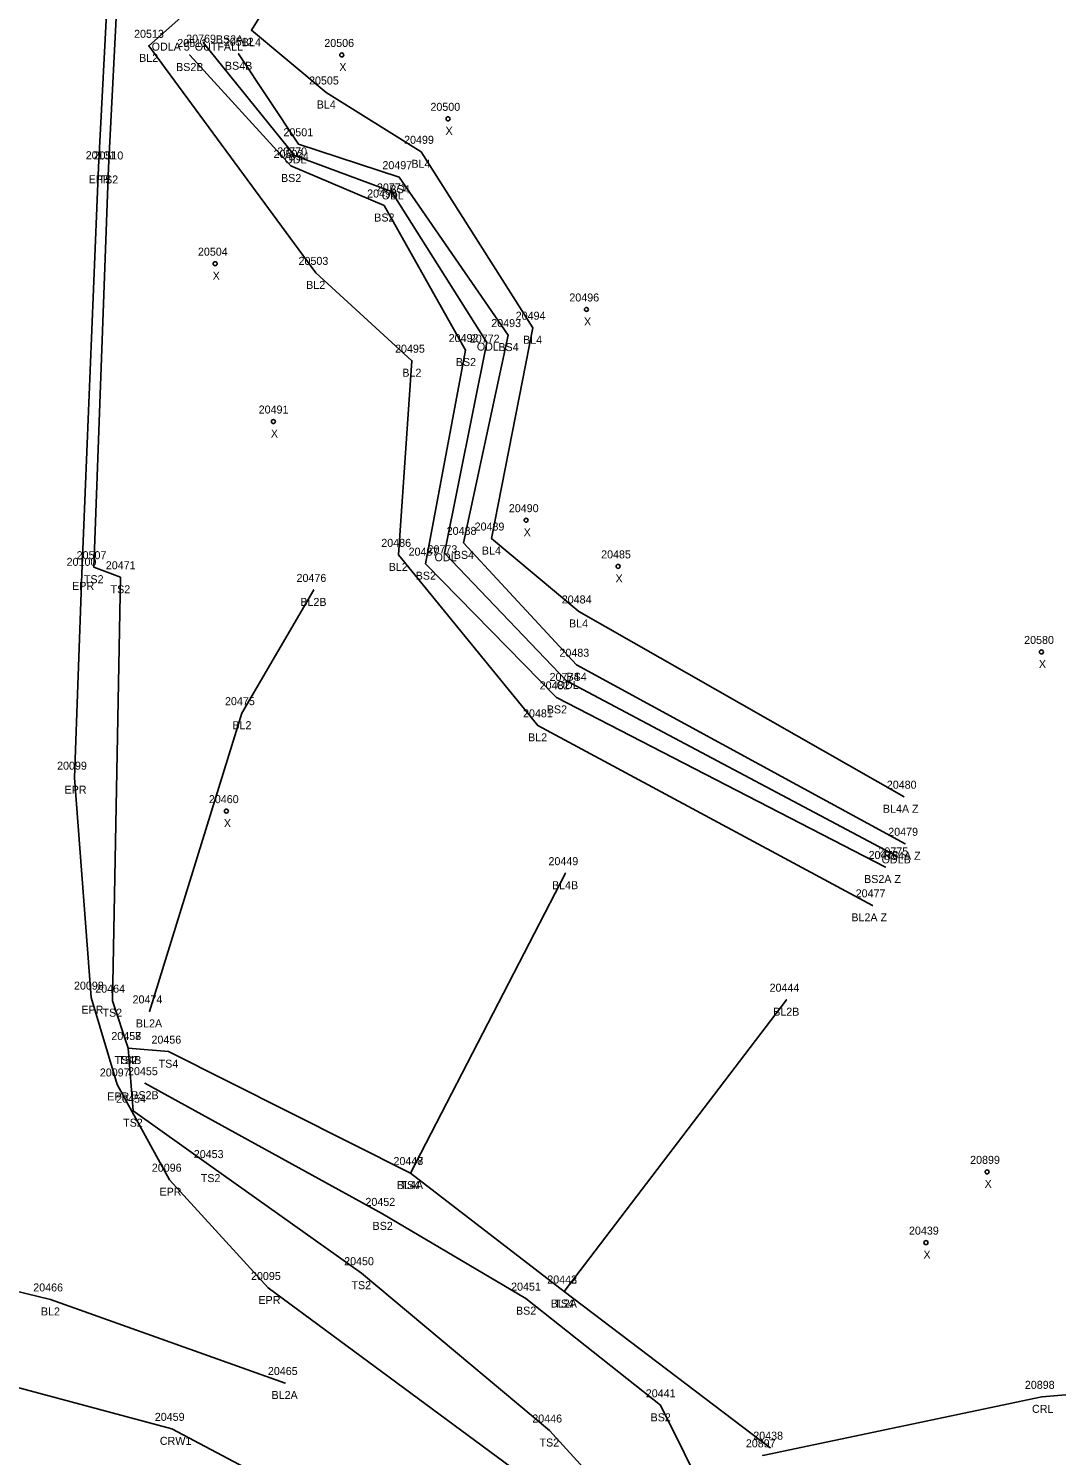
# Model space of a CAD drawing. Extents: x 1813127 to 1818290, y 1178171 to 1179900.
# Drawn here: x 1813676.1 to 1813804.5, y 1178739.3 to 1178917.6 of the extents above; entities that cross this region are included whole.
import ezdxf

# ---------------------------------------------------------------- set-up
doc = ezdxf.new("R2010")
doc.units = 0
for name, color, linetype in [('RD_DTM_BkLn1', 7, 'Continuous'), ('RD_DTM_BkLn2', 7, 'Continuous'), ('RD_EX_H2O', 7, 'Continuous'), ('RD_EX_H2O_txCode', 7, 'Continuous'), ('RD_EX_Road', 7, 'Continuous'), ('RD_EX_Road_txCode', 7, 'Continuous'), ('RD_SMD_Locator', 7, 'Continuous'), ('RD_SMD_Misc', 7, 'Continuous')]:
    doc.layers.add(name, color=color, linetype=linetype)

msp = doc.modelspace()

# ---------------------------------------------------------------- linework, layer by layer
at = {"layer": 'RD_DTM_BkLn1'}
for p, q in [((1813723.8, 1178774.61), (1813743.17, 1178812.08)), ((1813743.02, 1178759.81), (1813770.8, 1178796.27))]:
    msp.add_line(p, q, dxfattribs=at)
for points in [[(1813781.56, 1178808.06), (1813739.7, 1178830.55), (1813722.3, 1178851.85), (1813723.99, 1178876.11), (1813711.97, 1178887.08), (1813691.11, 1178915.45), (1813696.21, 1178919.94), (1813693.36, 1178948.36), (1813696.93, 1178995.1), (1813702.43, 1179045.97)], [(1813785.49, 1178821.63), (1813744.83, 1178844.78), (1813733.94, 1178853.89), (1813739.08, 1178880.23), (1813725.13, 1178902.21), (1813713.29, 1178909.62), (1813703.94, 1178917.4), (1813725.9, 1178952.77), (1813719.6, 1178998.9)], [(1813740.76, 1178717.86), (1813693.97, 1178742.65), (1813652.18, 1178753.85), (1813643.74, 1178755.64), (1813595, 1178763.51), (1813546.44, 1178770.61), (1813497.6, 1178777.62), (1813448.59, 1178785.89), (1813401.09, 1178795.04), (1813353.48, 1178806.76), (1813306.05, 1178819.85), (1813260.03, 1178834.12), (1813213.64, 1178849.47), (1813166.61, 1178866.29)], [(1813691.19, 1178794.81), (1813702.75, 1178832.07), (1813711.71, 1178847.47)], [(1813708.13, 1178748.38), (1813678.84, 1178758.82), (1813655.66, 1178764.45)]]:
    msp.add_lwpolyline(points, dxfattribs=at)
at = {"layer": 'RD_DTM_BkLn2'}
for points in [[(1813751.85, 1178730.74), (1813741.17, 1178742.44), (1813717.67, 1178762.1), (1813698.84, 1178775.48), (1813689.15, 1178782.4), (1813688.55, 1178790.23), (1813686.56, 1178796.15), (1813687.57, 1178849.05), (1813684.25, 1178850.31), (1813686.08, 1178900.25), (1813688.49, 1178947.42), (1813691.04, 1178995.37), (1813694.64, 1179045.56)], [(1813783.17, 1178812.85), (1813742.06, 1178834.04), (1813725.69, 1178850.75), (1813730.7, 1178877.44), (1813720.5, 1178895.5), (1813708.86, 1178900.44), (1813696.22, 1178914.3)], [(1813785.63, 1178815.75), (1813744.54, 1178838.12), (1813730.45, 1178853.35), (1813736.02, 1178879.31), (1813722.41, 1178899.04), (1813709.8, 1178903.15), (1813702.32, 1178914.46)], [(1813768.76, 1178740.3), (1813743.02, 1178759.81), (1813723.8, 1178774.61), (1813693.59, 1178789.78), (1813688.55, 1178790.23)], [(1813761, 1178733.6), (1813755.04, 1178745.59), (1813738.22, 1178758.92), (1813720.3, 1178769.51), (1813690.62, 1178785.84)]]:
    msp.add_lwpolyline(points, dxfattribs=at)
at = {"layer": 'RD_EX_H2O'}
for points in [[(1813697.92, 1178915.85), (1813709.32, 1178901.76), (1813721.45, 1178897.26), (1813733.34, 1178878.37), (1813728.06, 1178852.05), (1813743.31, 1178836.1), (1813784.4, 1178814.3)], [(1813767.83, 1178739.34), (1813802.7, 1178746.65), (1813832.24, 1178749.11), (1813880.12, 1178745.59), (1813913.04, 1178737.89)]]:
    msp.add_lwpolyline(points, dxfattribs=at)
at = {"layer": 'RD_EX_Road'}
msp.add_lwpolyline([(1813750.48, 1178727.17), (1813739.94, 1178735.23), (1813706.04, 1178760.25), (1813693.68, 1178773.78), (1813687.15, 1178785.68), (1813683.91, 1178796.53), (1813681.81, 1178824.01), (1813682.76, 1178849.48), (1813684.82, 1178900.28), (1813687.23, 1178946.66), (1813689.58, 1178995.92), (1813691.79, 1179045.45)], dxfattribs=at)
at = {"layer": 'RD_SMD_Locator'}
for centre, radius in [((1813703.94, 1178917.4), 0.001), ((1813691.11, 1178915.45), 0.001), ((1813697.92, 1178915.85), 0.001), ((1813696.22, 1178914.3), 0.001), ((1813702.32, 1178914.46), 0.001), ((1813715.22, 1178914.31), 0.25), ((1813713.29, 1178909.62), 0.001), ((1813728.5, 1178906.33), 0.25), ((1813709.8, 1178903.15), 0.001), ((1813709.32, 1178901.76), 0.001), ((1813725.13, 1178902.21), 0.001), ((1813684.82, 1178900.28), 0.001), ((1813686.08, 1178900.25), 0.001), ((1813708.86, 1178900.44), 0.001), ((1813722.41, 1178899.04), 0.001), ((1813721.45, 1178897.26), 0.001), ((1813720.5, 1178895.5), 0.001), ((1813699.4, 1178888.23), 0.25), ((1813711.97, 1178887.08), 0.001), ((1813745.8, 1178882.51), 0.25), ((1813736.02, 1178879.31), 0.001), ((1813739.08, 1178880.23), 0.001), ((1813733.34, 1178878.37), 0.001), ((1813723.99, 1178876.11), 0.001), ((1813730.7, 1178877.44), 0.001), ((1813706.67, 1178868.51), 0.25), ((1813738.26, 1178856.18), 0.25), ((1813730.45, 1178853.35), 0.001), ((1813733.94, 1178853.89), 0.001), ((1813722.3, 1178851.85), 0.001), ((1813728.06, 1178852.05), 0.001), ((1813682.76, 1178849.48), 0.001), ((1813684.25, 1178850.31), 0.001), ((1813687.57, 1178849.05), 0.001), ((1813725.69, 1178850.75), 0.001), ((1813749.75, 1178850.41), 0.25), ((1813711.71, 1178847.47), 0.001), ((1813744.83, 1178844.78), 0.001), ((1813802.65, 1178839.72), 0.25), ((1813744.54, 1178838.12), 0.001), ((1813743.31, 1178836.1), 0.001), ((1813742.06, 1178834.04), 0.001), ((1813702.75, 1178832.07), 0.001), ((1813739.7, 1178830.55), 0.001), ((1813681.81, 1178824.01), 0.001), ((1813785.49, 1178821.63), 0.001), ((1813700.8, 1178819.83), 0.25), ((1813785.63, 1178815.75), 0.001), ((1813784.4, 1178814.3), 0.001), ((1813743.17, 1178812.08), 0.001), ((1813783.17, 1178812.85), 0.001), ((1813781.56, 1178808.06), 0.001), ((1813683.91, 1178796.53), 0.001), ((1813686.56, 1178796.15), 0.001), ((1813770.8, 1178796.27), 0.001), ((1813691.19, 1178794.81), 0.001), ((1813688.55, 1178790.23), 0.001), ((1813688.55, 1178790.23), 0.001), ((1813693.59, 1178789.78), 0.001), ((1813687.15, 1178785.68), 0.001), ((1813690.62, 1178785.84), 0.001), ((1813689.15, 1178782.4), 0.001), ((1813698.84, 1178775.48), 0.001), ((1813723.8, 1178774.61), 0.001), ((1813723.8, 1178774.61), 0.001), ((1813795.86, 1178774.76), 0.25), ((1813693.68, 1178773.78), 0.001), ((1813720.3, 1178769.51), 0.001), ((1813788.22, 1178765.92), 0.25), ((1813717.67, 1178762.1), 0.001), ((1813706.04, 1178760.25), 0.001), ((1813678.84, 1178758.82), 0.001), ((1813738.22, 1178758.92), 0.001), ((1813743.02, 1178759.81), 0.001), ((1813743.02, 1178759.81), 0.001), ((1813708.13, 1178748.38), 0.001), ((1813802.7, 1178746.65), 0.001), ((1813755.04, 1178745.59), 0.001), ((1813693.97, 1178742.65), 0.001), ((1813741.17, 1178742.44), 0.001), ((1813768.76, 1178740.3), 0.001), ((1813767.83, 1178739.34), 0.001)]:
    msp.add_circle(centre, radius, dxfattribs=at)

# ---------------------------------------------------------------- texts
at = {"layer": 'RD_EX_H2O_txCode'}
for s, p in [('20769', (1813695.78, 1178915.85)), ("ODLA 5' OUTFALL", (1813691.47, 1178914.85)), ('20770', (1813707.16, 1178901.76)), ('ODL', (1813708.07, 1178900.76)), ('20771', (1813719.62, 1178897.26)), ('ODL', (1813720.21, 1178896.26)), ('20772', (1813731.22, 1178878.37)), ('ODL', (1813732.1, 1178877.37)), ('20773', (1813725.94, 1178852.05)), ('ODL', (1813726.82, 1178851.05)), ('20774', (1813741.19, 1178836.1)), ('ODL', (1813742.07, 1178835.1)), ('20775', (1813782.28, 1178814.3)), ('ODLB', (1813782.68, 1178813.3)), ('20898', (1813800.58, 1178747.65)), ('CRL', (1813801.47, 1178744.65)), ('20897', (1813765.71, 1178740.34))]:
    msp.add_text(s, height=1, dxfattribs=at).set_placement(p)
at = {"layer": 'RD_EX_Road_txCode'}
for s, p in [('20101', (1813683.23, 1178901.28)), ('EPR', (1813683.59, 1178898.28)), ('20100', (1813680.84, 1178850.48)), ('EPR', (1813681.53, 1178847.48)), ('20099', (1813679.65, 1178825.01)), ('EPR', (1813680.58, 1178822.01)), ('20098', (1813681.76, 1178797.53)), ('EPR', (1813682.68, 1178794.53)), ('20097', (1813684.99, 1178786.68)), ('EPR', (1813685.92, 1178783.68)), ('20096', (1813691.49, 1178774.78)), ('EPR', (1813692.45, 1178771.78)), ('20095', (1813703.88, 1178761.25)), ('EPR', (1813704.81, 1178758.25))]:
    msp.add_text(s, height=1, dxfattribs=at).set_placement(p)
at = {"layer": 'RD_SMD_Misc'}
for s, p in [('20513', (1813689.27, 1178916.45)), ('BS2A', (1813699.49, 1178915.76)), ('20511', (1813694.67, 1178915.3)), ('20512', (1813700.48, 1178915.46)), ('BL4', (1813702.74, 1178915.4)), ('20506', (1813713.04, 1178915.31)), ('BL2', (1813689.9, 1178913.45)), ('BS2B', (1813694.52, 1178912.3)), ('BS4B', (1813700.62, 1178912.46)), ('X', (1813714.91, 1178912.31)), ('20505', (1813711.13, 1178910.62)), ('BL4', (1813712.09, 1178907.62)), ('20500', (1813726.3, 1178907.33)), ('20501', (1813707.93, 1178904.15)), ('X', (1813728.19, 1178904.33)), ('20499', (1813723.01, 1178903.21)), ('20510', (1813684.2, 1178901.25)), ('20502', (1813706.7, 1178901.44)), ('BS4', (1813708.57, 1178901.15)), ('20497', (1813720.3, 1178900.04)), ('BL4', (1813723.92, 1178900.21)), ('TS2', (1813684.83, 1178898.25)), ('BS2', (1813707.63, 1178898.44)), ('20498', (1813718.39, 1178896.5)), ('BS4', (1813721.19, 1178897.04)), ('BS2', (1813719.28, 1178893.5)), ('20504', (1813697.25, 1178889.23)), ('20503', (1813709.82, 1178888.08)), ('X', (1813699.09, 1178886.23)), ('BL2', (1813710.77, 1178885.08)), ('20496', (1813743.66, 1178883.51)), ('20493', (1813733.9, 1178880.31)), ('20494', (1813736.96, 1178881.23)), ('X', (1813745.49, 1178880.51)), ('20492', (1813728.58, 1178878.44)), ('20495', (1813721.88, 1178877.11)), ('BS4', (1813734.79, 1178877.31)), ('BL4', (1813737.88, 1178878.23)), ('BS2', (1813729.47, 1178875.44)), ('BL2', (1813722.79, 1178874.11)), ('20491', (1813704.84, 1178869.51)), ('X', (1813706.36, 1178866.51)), ('20490', (1813736.1, 1178857.18)), ('20488', (1813728.33, 1178854.35)), ('20489', (1813731.82, 1178854.89)), ('X', (1813737.95, 1178854.18)), ('20486', (1813720.16, 1178852.85)), ('20487', (1813723.57, 1178851.75)), ('BL4', (1813732.73, 1178851.89)), ('20507', (1813682.09, 1178851.31)), ('20471', (1813685.74, 1178850.05)), ('BL2', (1813721.09, 1178849.85)), ('BS4', (1813729.22, 1178851.35)), ('20485', (1813747.63, 1178851.41)), ('TS2', (1813683, 1178848.31)), ('20476', (1813709.57, 1178848.47)), ('BS2', (1813724.46, 1178848.75)), ('X', (1813749.43, 1178848.41)), ('TS2', (1813686.33, 1178847.05)), ('BL2B', (1813710.04, 1178845.47)), ('20484', (1813742.71, 1178845.78)), ('BL4', (1813743.62, 1178842.78)), ('20483', (1813742.42, 1178839.12)), ('20580', (1813800.49, 1178840.72)), ('X', (1813802.33, 1178837.72)), ('BS4', (1813743.31, 1178836.12)), ('20482', (1813739.95, 1178835.04)), ('20475', (1813700.63, 1178833.07)), ('BS2', (1813740.84, 1178832.04)), ('20481', (1813737.87, 1178831.55)), ('BL2', (1813701.55, 1178830.07)), ('BL2', (1813738.5, 1178828.55)), ('20480', (1813783.33, 1178822.63)), ('20460', (1813698.62, 1178820.83)), ('BL4A Z', (1813782.84, 1178819.63)), ('X', (1813700.49, 1178817.83)), ('20479', (1813783.51, 1178816.75)), ('20449', (1813741.05, 1178813.08)), ('20478', (1813781.05, 1178813.85)), ('BS4A Z', (1813782.95, 1178813.75)), ('BS2A Z', (1813780.49, 1178810.85)), ('BL4B', (1813741.49, 1178810.08)), ('20477', (1813779.44, 1178809.06)), ('BL2A Z', (1813778.9, 1178806.06)), ('20464', (1813684.42, 1178797.15)), ('20444', (1813768.68, 1178797.27)), ('20474', (1813689.08, 1178795.81)), ('TS2', (1813685.32, 1178794.15)), ('BL2A', (1813689.5, 1178792.81)), ('BL2B', (1813769.13, 1178794.27)), ('20457', (1813686.43, 1178791.23)), ('20458', (1813686.43, 1178791.23)), ('20456', (1813691.44, 1178790.78)), ('TS4B', (1813686.83, 1178788.23)), ('TS2', (1813687.3, 1178788.23)), ('TS4', (1813692.34, 1178787.78)), ('20455', (1813688.51, 1178786.84)), ('BS2B', (1813688.92, 1178783.84)), ('20454', (1813687.03, 1178783.4)), ('TS2', (1813687.9, 1178780.4)), ('20453', (1813696.73, 1178776.48)), ('20447', (1813721.68, 1178775.61)), ('20448', (1813721.68, 1178775.61)), ('20899', (1813793.74, 1178775.76)), ('TS2', (1813697.6, 1178773.48)), ('BL4A', (1813722.1, 1178772.61)), ('TS4', (1813722.55, 1178772.61)), ('X', (1813795.55, 1178772.76)), ('20452', (1813718.18, 1178770.51)), ('BS2', (1813719.07, 1178767.51)), ('20439', (1813786.1, 1178766.92)), ('20450', (1813715.52, 1178763.1)), ('X', (1813787.91, 1178763.92)), ('20442', (1813740.9, 1178760.81)), ('20443', (1813740.9, 1178760.81)), ('20466', (1813676.67, 1178759.82)), ('TS2', (1813716.43, 1178760.1)), ('20451', (1813736.38, 1178759.92)), ('BL2A', (1813741.33, 1178757.81)), ('TS4', (1813741.78, 1178757.81)), ('BL2', (1813677.63, 1178756.82)), ('BS2', (1813736.99, 1178756.92)), ('20465', (1813705.99, 1178749.38)), ('BL2A', (1813706.44, 1178746.38)), ('20441', (1813753.21, 1178746.59)), ('20459', (1813691.86, 1178743.65)), ('20446', (1813739.03, 1178743.44)), ('BS2', (1813753.81, 1178743.59)), ('20438', (1813766.64, 1178741.3)), ('CRW1', (1813692.49, 1178740.65)), ('TS2', (1813739.93, 1178740.44))]:
    msp.add_text(s, height=1, dxfattribs=at).set_placement(p)

doc.saveas('drawing.dxf')
